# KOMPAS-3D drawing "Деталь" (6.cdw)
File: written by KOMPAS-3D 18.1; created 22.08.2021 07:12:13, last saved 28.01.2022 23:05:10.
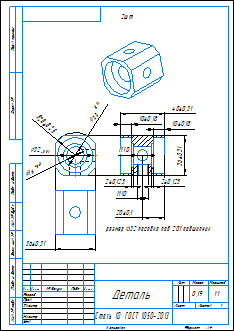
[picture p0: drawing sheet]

Sheet 1: A4, portrait

Document properties: Автор: 111; Полное имя файла: C:\Users\admin\Desktop\ffb\6.cdw; Масса: 0.194146

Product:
- Part/product: Деталь
    Масса: 0.194146
    source file: ..\1.cdw
  - Component: Наружная резьба
  - Component: Отверстие  | qty 4

Title block, sheet 1: Наименование: Деталь; Материал: Сталь 10  ГОСТ 1050-2013; Масса: 0,19; Количество листов документа: 1; Форматы листов документа: A4; stored path: C:\Users\admin\Desktop\ffb\Новая папка\1.cdw

Views: Вид 2, Спереди, Вид 4, Снизу
Referenced files in C:\Users\admin\Desktop\ffb\Новая папка\: D_.m3d
Referenced files in H:\Desktop\_\: D.m3d
Referenced files in C:\Users\admin\Desktop\ffb\: D.m3d
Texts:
  Отверстие
  размер Ø32 посадка под 201 подшипник
Dimensions and other numbers on the sheet: 40±0,31; 10±0,18; 20±0,1; 2шт.; 2±0,125; 36±0,31; 32; 22; 16; 1:1; 1; 0,19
